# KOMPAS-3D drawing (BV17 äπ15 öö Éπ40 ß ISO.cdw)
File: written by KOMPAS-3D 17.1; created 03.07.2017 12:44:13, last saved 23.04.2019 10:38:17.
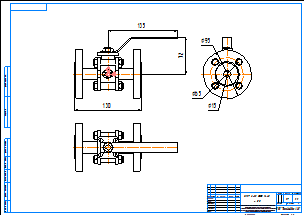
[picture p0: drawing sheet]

Sheet 1: A2, landscape

Title block, sheet 1: name: BV17 Ду15 ФФ Ру40 / с ISO; material: Внимание! Данный продукт является объектом авторского права ООО «Торговый Дом АДЛ». / Запрещается изменение, копирование, распространение / (в том числе путем копирования на другие сайты и ресурсы в Интернете) / или любое иное использование информации и объектов без предварительного / согласия правообладателя (ООО «Торговый Дом АДЛ»).; mass: 1,7; sheets: 1; organisation: ООО "Торговый дом АДЛ"; sheet format: A2; stored path: C:\Users\kka\KOMPAS_Work\!Trash\СС02 СС03 ФФ Смотровые стекла\СС01.cdw

Views: Спереди 1, Проекционный вид 2, Проекционный вид 3
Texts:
  Klimkovich
  ADL
Dimensions and other numbers on the sheet: 130; 135; 72; 65; 95; 15; 1:1; 1; 1,7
